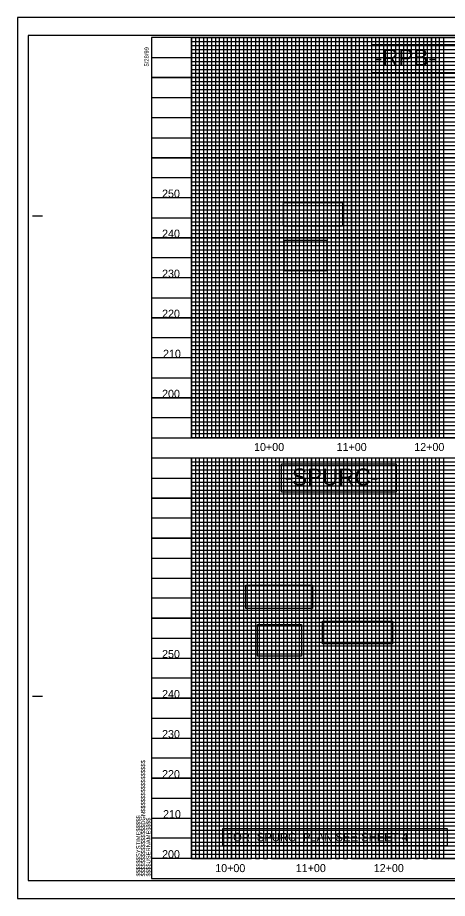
# Model space of a CAD drawing. Extents: x 1810963 to 1812960, y 722070 to 723170.
# Drawn here: x 1810963 to 1811500, y 722070 to 723170 of the extents above; entities that cross this region are included whole.
import ezdxf

# ---------------------------------------------------------------- set-up
doc = ezdxf.new("R2010")
doc.units = 0
for name, color, linetype in [('Exist Horizontal Alignment Tick Label', 7, 'Continuous'), ('Old_Level_11', 7, 'Continuous'), ('Old_Level_2', 7, 'Continuous'), ('Prop Conc 2ft 6in Curb and Gutter', 7, 'Continuous'), ('Prop RDY Traffic Signal CELL', 7, 'Continuous'), ('Prop Shade Heavy', 7, 'Continuous'), ('Prop Shade Light', 7, 'Continuous'), ('Scratch_Level_0', 7, 'Continuous'), ('Scratch_Level_3', 7, 'Continuous'), ('Sheet Block Title CELL', 7, 'Continuous'), ('Sheet Layout Profile Border Port 1', 7, 'Continuous'), ('Sheet Layout Profile Border Port 2', 7, 'Continuous'), ('Sheet North Arrow CELL', 7, 'Continuous'), ('Sheet Symbology CELL', 7, 'Continuous'), ('Sheet Title CELL', 7, 'Continuous')]:
    doc.layers.add(name, color=color, linetype=linetype)

msp = doc.modelspace()

# ---------------------------------------------------------------- linework, layer by layer
at = {"layer": 'Old_Level_11'}
msp.add_lwpolyline([(1810976.5, 722092.3), (1812643, 722092.3), (1812643, 723147.4), (1810976.5, 723147.4)], close=True, dxfattribs=at)
at = {"layer": 'Old_Level_2'}
for points in [[(1811405.7, 723136.4), (1811513.8, 723136.4), (1811513.8, 723101.1), (1811405.7, 723101.1)], [(1811295.4, 722938.9), (1811369.1, 722938.9), (1811369.1, 722909.6), (1811295.4, 722909.6)], [(1811296.2, 722891.9), (1811349.9, 722891.9), (1811349.9, 722853.7), (1811296.2, 722853.7)], [(1811292.9, 722612.7), (1811436.3, 722612.7), (1811436.3, 722577.3), (1811292.9, 722577.3)], [(1811248.4, 722460.9), (1811331.9, 722460.9), (1811331.9, 722431.9), (1811248.4, 722431.9)], [(1811344.1, 722416.3), (1811431.9, 722416.3), (1811431.9, 722388), (1811344.1, 722388)], [(1811263.3, 722411.8), (1811318.2, 722411.8), (1811318.2, 722372.5), (1811263.3, 722372.5)], [(1811219.7, 722157), (1811500.2, 722157), (1811500.2, 722135.4), (1811219.7, 722135.4)]]:
    msp.add_lwpolyline(points, close=True, dxfattribs=at)
at = {"layer": 'Prop Conc 2ft 6in Curb and Gutter'}
for p, q in [((1811180.5, 722644.9), (1811180.5, 723144.9)), ((1811230.5, 722644.9), (1811230.5, 723144.9)), ((1811280.5, 722644.9), (1811280.5, 723144.9)), ((1811330.5, 722644.9), (1811330.5, 723144.9)), ((1811380.5, 722644.9), (1811380.5, 723144.9)), ((1811430.5, 722644.9), (1811430.5, 723144.9)), ((1811480.5, 722644.9), (1811480.5, 723144.9)), ((1812230.4, 723094.9), (1811130.5, 723094.9)), ((1812430.4, 723044.9), (1811130.5, 723044.9)), ((1812430.5, 722994.9), (1811130.5, 722994.9)), ((1812630.5, 722944.9), (1811130.5, 722944.9)), ((1812630.5, 722894.9), (1811130.5, 722894.9)), ((1812630.5, 722844.9), (1811130.5, 722844.9)), ((1812630.5, 722794.9), (1811130.5, 722794.9)), ((1812630.5, 722744.9), (1811130.5, 722744.9)), ((1812630.5, 722694.9), (1811130.5, 722694.9)), ((1811130.5, 722619.9), (1812630.3, 722619.9)), ((1811180.5, 722619.9), (1811180.5, 722119.9)), ((1811230.5, 722619.9), (1811230.5, 722119.9)), ((1811280.5, 722619.9), (1811280.5, 722119.9)), ((1811330.5, 722619.9), (1811330.5, 722119.9)), ((1811380.5, 722619.9), (1811380.5, 722119.9)), ((1811430.5, 722619.9), (1811430.5, 722119.9)), ((1811480.5, 722619.9), (1811480.5, 722119.9)), ((1811130.5, 722569.9), (1812630.3, 722569.9)), ((1811130.5, 722519.9), (1812630.3, 722519.9)), ((1811130.5, 722469.9), (1812630.3, 722469.9)), ((1811130.5, 722419.9), (1812630.3, 722419.9)), ((1811130.5, 722369.9), (1812630.3, 722369.9)), ((1811130.5, 722319.9), (1812630.3, 722319.9)), ((1811130.5, 722269.9), (1812630.3, 722269.9)), ((1811130.5, 722219.9), (1812630.3, 722219.9)), ((1811130.5, 722169.9), (1812630.3, 722169.9))]:
    msp.add_line(p, q, dxfattribs=at)
at = {"layer": 'Prop RDY Traffic Signal CELL'}
for p, q in [((1812647.5, 723169.9), (1810963.5, 723169.9)), ((1810963.5, 723169.9), (1810963.5, 722069.9)), ((1810963.5, 722069.9), (1812647.5, 722069.9))]:
    msp.add_line(p, q, dxfattribs=at)
at = {"layer": 'Prop Shade Heavy'}
msp.add_line((1811130.5, 722119.9), (1811130.5, 722119.9), dxfattribs=at)
for points in [[(1811180.5, 723144.9), (1811180.5, 722644.9), (1811230.5, 722644.9), (1811230.5, 723144.9), (1811280.5, 723144.9), (1811280.5, 722644.9), (1811330.5, 722644.9), (1811330.5, 723144.9), (1811380.5, 723144.9), (1811380.5, 722644.9), (1811430.5, 722644.9), (1811430.5, 723144.9), (1811480.5, 723144.9), (1811480.5, 722644.9), (1811530.5, 722644.9)], [(1811130.5, 723094.9), (1812230.4, 723094.9)], [(1812430.5, 723044.9), (1811130.5, 723044.9), (1811130.5, 722994.9), (1812430.5, 722994.9)], [(1812630.5, 722944.9), (1811130.5, 722944.9), (1811130.5, 722894.9), (1812630.5, 722894.9)], [(1812630.5, 722844.9), (1811130.5, 722844.9), (1811130.5, 722794.9), (1812630.5, 722794.9)], [(1812630.5, 722744.9), (1811130.5, 722744.9), (1811130.5, 722744.9), (1811130.5, 722694.9), (1812630.5, 722694.9)], [(1811180.5, 722619.9), (1811180.5, 722119.9), (1811230.5, 722119.9), (1811230.5, 722619.9), (1811280.5, 722619.9), (1811280.5, 722119.9), (1811330.5, 722119.9), (1811330.5, 722619.9), (1811380.5, 722619.9), (1811380.5, 722119.9), (1811430.5, 722119.9), (1811430.5, 722619.9), (1811480.5, 722619.9), (1811480.5, 722119.9), (1811530.5, 722119.9)], [(1812630.5, 722569.9), (1811130.5, 722569.9)], [(1812630.5, 722519.9), (1811130.5, 722519.9), (1811130.5, 722469.9), (1812630.5, 722469.9)], [(1812630.5, 722419.9), (1811130.5, 722419.9), (1811130.5, 722369.9), (1812630.5, 722369.9)], [(1812630.5, 722319.9), (1811130.5, 722319.9), (1811130.5, 722269.9), (1812630.5, 722269.9)], [(1812630.5, 722219.9), (1811130.5, 722219.9), (1811130.5, 722219.9), (1811130.5, 722169.9), (1812630.5, 722169.9)], [(1812630.5, 722119.9), (1811130.5, 722119.9)]]:
    msp.add_lwpolyline(points, dxfattribs=at)
at = {"layer": 'Prop Shade Light'}
for p, q in [((1811205.5, 723144.9), (1811205.5, 722644.9)), ((1811255.5, 722644.9), (1811255.5, 723144.9)), ((1811255.5, 723144.9), (1811305.5, 723144.9)), ((1811305.5, 723144.9), (1811305.5, 722644.9)), ((1811355.5, 722644.9), (1811355.5, 723144.9)), ((1811355.5, 723144.9), (1811405.5, 723144.9)), ((1811405.5, 723144.9), (1811405.5, 722644.9)), ((1811455.5, 722644.9), (1811455.5, 723144.9)), ((1811455.5, 723144.9), (1811505.5, 723144.9)), ((1811130.5, 723119.9), (1812230.4, 723119.9)), ((1811205.5, 722644.9), (1811255.5, 722644.9)), ((1811305.5, 722644.9), (1811355.5, 722644.9)), ((1811405.5, 722644.9), (1811455.5, 722644.9))]:
    msp.add_line(p, q, dxfattribs=at)
for points in [[(1812430.5, 723069.9), (1811130.5, 723069.9), (1811130.5, 723019.9), (1812430.5, 723019.9)], [(1812630.5, 722969.9), (1811130.5, 722969.9), (1811130.5, 722919.9), (1812455.5, 722919.9)], [(1812630.5, 722869.9), (1811130.5, 722869.9), (1811130.5, 722819.9), (1812630.5, 722819.9)], [(1812630.5, 722769.9), (1811130.5, 722769.9), (1811130.5, 722719.9), (1812630.5, 722719.9)], [(1812630.5, 722669.9), (1811130.5, 722669.9)], [(1811155.5, 722619.9), (1811205.5, 722619.9), (1811205.5, 722119.9), (1811255.5, 722119.9), (1811255.5, 722619.9), (1811305.5, 722619.9), (1811305.5, 722119.9), (1811355.5, 722119.9), (1811355.5, 722619.9), (1811405.5, 722619.9), (1811405.5, 722119.9), (1811455.5, 722119.9), (1811455.5, 722619.9), (1811505.5, 722619.9)], [(1811130.5, 722594.9), (1812630.5, 722594.9)], [(1812630.5, 722544.9), (1811130.5, 722544.9), (1811130.5, 722494.9), (1812630.5, 722494.9)], [(1812630.5, 722444.9), (1811130.5, 722444.9), (1811130.5, 722394.9), (1812630.5, 722394.9)], [(1812630.5, 722344.9), (1811130.5, 722344.9), (1811130.5, 722294.9), (1812630.5, 722294.9)], [(1812630.5, 722244.9), (1811130.5, 722244.9), (1811130.5, 722194.9), (1812630.5, 722194.9)], [(1812630.5, 722144.9), (1811130.5, 722144.9)]]:
    msp.add_lwpolyline(points, dxfattribs=at)
at = {"layer": 'Scratch_Level_3'}
msp.add_lwpolyline([(1811180.5, 723144.9), (1812230.5, 723144.9), (1812230.5, 723092.4), (1812430.5, 723092.4), (1812430.4, 722983.8), (1812580.5, 722983.8), (1812580.5, 722644.9), (1811180.5, 722644.9)], close=True, dxfattribs=at)
at = {"layer": 'Sheet Layout Profile Border Port 1'}
msp.add_lwpolyline([(1811180.5, 722983.8), (1811180.5, 722644.9), (1812580.5, 722644.9), (1812580.5, 722983.8)], dxfattribs=at)
at = {"layer": 'Sheet Layout Profile Border Port 2'}
msp.add_lwpolyline([(1811180.5, 722619.9), (1812580.5, 722619.9), (1812580.5, 722119.9), (1811180.5, 722119.9)], close=True, dxfattribs=at)
at = {"layer": 'Sheet North Arrow CELL'}
msp.add_lwpolyline([(1810963.5, 722069.9), (1812647.5, 722069.9), (1812647.5, 723169.9), (1810963.5, 723169.9)], close=True, dxfattribs=at)
at = {"layer": 'Sheet Symbology CELL'}
for p, q in [((1810982, 722922.4), (1810994.5, 722922.4)), ((1811130.5, 722644.9), (1812630.5, 722644.9)), ((1811130.5, 722619.9), (1812630.5, 722619.9)), ((1810982, 722322.4), (1810994.5, 722322.4)), ((1812630.5, 722119.9), (1811130.5, 722119.9)), ((1811130.5, 722094.9), (1812630.5, 722094.9)), ((1811130.5, 722094.9), (1811130.5, 722094.9)), ((1811130.5, 722094.9), (1811130.5, 722094.9)), ((1811130.5, 722094.9), (1811130.5, 722094.9)), ((1811130.5, 722094.9), (1811130.5, 722094.9)), ((1811130.5, 722094.9), (1811130.5, 722094.9)), ((1811130.5, 722094.9), (1811130.5, 722094.9)), ((1811130.5, 722094.9), (1811130.5, 722094.9))]:
    msp.add_line(p, q, dxfattribs=at)
msp.add_lwpolyline([(1812630.5, 723144.9), (1811130.5, 723144.9), (1811130.5, 722094.9), (1812630.5, 722094.9)], close=True, dxfattribs=at)
msp.add_lwpolyline([(1811161, 722094.9), (1811161, 722094.9)], dxfattribs=at)
at = {"layer": 'Sheet Title CELL'}
for p, q in [((1811180.5, 723139.9), (1812230.4, 723139.9)), ((1811180.5, 723134.9), (1811180.5, 723134.9)), ((1812230.4, 723134.8), (1811180.5, 723134.5)), ((1811180.5, 723129.9), (1812230.4, 723129.9)), ((1812230.4, 723099.9), (1811180.5, 723099.9)), ((1811180.5, 723099.9), (1811180.5, 723089.9)), ((1811180.5, 723089.9), (1812430.5, 723089.9)), ((1812430.4, 723009.9), (1811180.5, 723009.9)), ((1812430.5, 723004.9), (1811180.5, 723004.9)), ((1812430.5, 722999.9), (1811180.5, 722999.9)), ((1811180.5, 722989.9), (1812430.5, 722989.9)), ((1812430.5, 722984.9), (1811180.5, 722984.9)), ((1811180.5, 722979.9), (1812580.5, 722979.9)), ((1812580.5, 722959.9), (1811180.5, 722959.9)), ((1811180.5, 722954.9), (1812580.5, 722954.9)), ((1812580.5, 722934.9), (1811180.5, 722934.9)), ((1811180.5, 722929.9), (1812580.5, 722929.9)), ((1812580.5, 722909.9), (1811180.5, 722909.9)), ((1811180.5, 722904.9), (1812580.5, 722904.9)), ((1812580.5, 722899.9), (1811180.5, 722899.9)), ((1811180.5, 722889.9), (1812580.5, 722889.9)), ((1812580.5, 722884.9), (1811180.5, 722884.9)), ((1811180.5, 722879.9), (1812580.5, 722879.9)), ((1812580.5, 722874.9), (1811180.5, 722874.9)), ((1811180.5, 722864.9), (1812580.5, 722864.9)), ((1812580.5, 722859.9), (1811180.5, 722859.9)), ((1811180.5, 722854.9), (1812580.5, 722854.9)), ((1812580.5, 722849.9), (1811180.5, 722849.9)), ((1811180.5, 722839.9), (1812580.5, 722839.9)), ((1812580.5, 722834.9), (1811180.5, 722834.9)), ((1811180.5, 722829.9), (1812580.5, 722829.9)), ((1812580.5, 722824.9), (1811180.5, 722824.9)), ((1811180.5, 722814.9), (1812580.5, 722814.9)), ((1812580.5, 722809.9), (1811180.5, 722809.9)), ((1811180.5, 722804.9), (1812580.5, 722804.9)), ((1812580.5, 722799.9), (1811180.5, 722799.9)), ((1811180.5, 722789.9), (1812580.5, 722789.9)), ((1812580.5, 722784.9), (1811180.5, 722784.9)), ((1811180.5, 722779.9), (1812580.5, 722779.9)), ((1812580.5, 722774.9), (1811180.5, 722774.9)), ((1811180.5, 722764.9), (1812580.5, 722764.9)), ((1812580.5, 722759.9), (1811180.5, 722759.9)), ((1812580.5, 722754.9), (1811180.5, 722754.9)), ((1812580.5, 722749.9), (1811180.5, 722749.9)), ((1811180.5, 722739.9), (1812580.5, 722739.9)), ((1812580.5, 722734.9), (1811180.5, 722734.9)), ((1811180.5, 722729.9), (1812580.5, 722729.9)), ((1812580.5, 722724.9), (1811180.5, 722724.9)), ((1811180.5, 722714.9), (1812580.5, 722714.9)), ((1812580.5, 722709.9), (1811180.5, 722709.9)), ((1811180.5, 722704.9), (1812580.5, 722704.9)), ((1812580.5, 722699.9), (1811180.5, 722699.9)), ((1811180.5, 722689.9), (1812580.5, 722689.9)), ((1812580.5, 722684.9), (1811180.5, 722684.9)), ((1811180.5, 722679.9), (1812580.5, 722679.9)), ((1812580.5, 722674.9), (1811180.5, 722674.9)), ((1811180.5, 722664.9), (1812580.5, 722664.9)), ((1812580.5, 722659.9), (1811180.5, 722659.9)), ((1811180.5, 722654.9), (1812580.5, 722654.9)), ((1811180.5, 722614.9), (1812580.5, 722614.9)), ((1812580.5, 722609.9), (1811180.5, 722609.9)), ((1811180.5, 722604.9), (1812580.5, 722604.9)), ((1812580.5, 722599.9), (1811180.5, 722599.9)), ((1811180.5, 722589.9), (1812580.5, 722589.9)), ((1812580.5, 722584.9), (1811180.5, 722584.9)), ((1811180.5, 722579.9), (1812580.5, 722579.9)), ((1812580.5, 722574.9), (1811180.5, 722574.9)), ((1811180.5, 722564.9), (1812580.5, 722564.9)), ((1812580.5, 722559.9), (1811180.5, 722559.9)), ((1811180.5, 722554.9), (1812580.5, 722554.9)), ((1812580.5, 722549.9), (1811180.5, 722549.9)), ((1811180.5, 722539.9), (1812580.5, 722539.9)), ((1812580.5, 722534.9), (1811180.5, 722534.9)), ((1811180.5, 722529.9), (1812580.5, 722529.9)), ((1812580.5, 722524.9), (1811180.5, 722524.9)), ((1811180.5, 722514.9), (1812580.5, 722514.9)), ((1812580.5, 722509.9), (1811180.5, 722509.9)), ((1811180.5, 722504.9), (1812580.5, 722504.9)), ((1812580.5, 722499.9), (1811180.5, 722499.9)), ((1811180.5, 722489.9), (1812580.5, 722489.9)), ((1812580.5, 722484.9), (1811180.5, 722484.9)), ((1811180.5, 722479.9), (1812580.5, 722479.9)), ((1812580.5, 722474.9), (1811180.5, 722474.9)), ((1811180.5, 722464.9), (1812580.5, 722464.9)), ((1812580.5, 722459.9), (1811180.5, 722459.9)), ((1811180.5, 722454.9), (1812580.5, 722454.9)), ((1812580.5, 722449.9), (1811180.5, 722449.9)), ((1811180.5, 722439.9), (1812580.5, 722439.9)), ((1812580.5, 722434.9), (1811180.5, 722434.9)), ((1811180.5, 722429.9), (1812580.5, 722429.9)), ((1812580.5, 722424.9), (1811180.5, 722425)), ((1811180.5, 722414.9), (1812580.5, 722414.9)), ((1812580.5, 722409.9), (1811180.5, 722409.9)), ((1811180.5, 722404.9), (1812580.5, 722404.9)), ((1812580.5, 722399.9), (1811180.5, 722399.9)), ((1811180.5, 722389.9), (1812580.5, 722389.9)), ((1812580.5, 722384.9), (1811180.5, 722384.9)), ((1811180.5, 722379.9), (1812580.5, 722379.9)), ((1812580.5, 722374.9), (1811180.5, 722374.9)), ((1811180.5, 722364.9), (1812580.5, 722364.9)), ((1812580.5, 722359.9), (1811180.5, 722359.9)), ((1811180.5, 722354.9), (1812580.5, 722354.9)), ((1812580.5, 722349.9), (1811180.5, 722349.9)), ((1811180.5, 722339.9), (1812580.5, 722339.9)), ((1812580.5, 722334.9), (1811180.5, 722334.9)), ((1811180.5, 722329.9), (1812580.5, 722329.9)), ((1812580.5, 722324.9), (1811180.5, 722324.9)), ((1811180.5, 722314.9), (1812580.5, 722314.9)), ((1812580.5, 722309.9), (1811180.5, 722309.9)), ((1811180.5, 722304.9), (1812580.5, 722304.9)), ((1812580.5, 722299.9), (1811180.5, 722299.9)), ((1811180.5, 722289.9), (1812580.5, 722289.9)), ((1812580.5, 722284.9), (1811180.5, 722284.9)), ((1811180.5, 722279.9), (1812580.5, 722279.9)), ((1812580.5, 722274.9), (1811180.5, 722274.9)), ((1811180.5, 722264.9), (1812580.5, 722264.9)), ((1812580.5, 722259.9), (1811180.5, 722259.9)), ((1811180.5, 722254.9), (1812580.5, 722254.9)), ((1812580.5, 722249.9), (1811180.5, 722249.9)), ((1811180.5, 722239.9), (1812580.5, 722239.9)), ((1812580.5, 722234.9), (1811180.5, 722234.9)), ((1811180.5, 722229.9), (1812580.5, 722229.9)), ((1812580.5, 722224.9), (1811180.5, 722224.9)), ((1811180.5, 722214.9), (1812580.5, 722214.9)), ((1812580.5, 722209.9), (1811180.5, 722209.9)), ((1811180.5, 722204.9), (1812580.5, 722204.9)), ((1812580.5, 722199.9), (1811180.5, 722199.9)), ((1811180.5, 722189.9), (1812580.5, 722189.9)), ((1812580.5, 722184.9), (1811180.5, 722184.9)), ((1811180.5, 722179.9), (1812580.5, 722179.9)), ((1812580.5, 722174.9), (1811180.5, 722174.9)), ((1811180.5, 722164.9), (1812580.5, 722164.9)), ((1812580.5, 722159.9), (1811180.5, 722159.9)), ((1811180.5, 722154.9), (1812580.5, 722154.9)), ((1812580.5, 722149.9), (1811180.5, 722149.9)), ((1811180.5, 722139.9), (1812580.5, 722139.9)), ((1812580.5, 722134.9), (1811180.5, 722134.9)), ((1811180.5, 722129.9), (1812580.5, 722129.9)), ((1811180.5, 722124.9), (1812580.5, 722124.9))]:
    msp.add_line(p, q, dxfattribs=at)
for points in [[(1811185.5, 723144.9), (1811185.5, 722644.9), (1811190.5, 722644.9), (1811190.5, 723144.9), (1811195.5, 723144.9), (1811195.5, 722644.9), (1811200.5, 722644.9), (1811200.5, 723144.9), (1811210.5, 723144.9), (1811210.5, 722644.9), (1811215.5, 722644.9), (1811215.5, 723144.9), (1811220.5, 723144.9), (1811220.5, 722644.9), (1811225.5, 722644.9), (1811235.5, 722644.9), (1811240.5, 722644.9), (1811240.5, 723144.9), (1811245.5, 723144.9), (1811245.5, 722644.9), (1811250.5, 722644.9), (1811250.5, 723144.9), (1811260.5, 723144.9), (1811260.5, 722644.9), (1811265.5, 722644.9), (1811265.5, 723144.9), (1811270.5, 723144.9), (1811270.5, 722644.9), (1811275.5, 722644.9), (1811275.5, 723144.9), (1811285.5, 723144.9), (1811285.5, 722644.9), (1811290.5, 722644.9), (1811290.5, 723144.9), (1811295.5, 723144.9), (1811295.5, 722644.9), (1811300.5, 722644.9), (1811300.5, 723144.9), (1811310.5, 723144.9), (1811310.5, 722644.9), (1811315.5, 722644.9), (1811315.5, 723144.9), (1811320.5, 723144.9), (1811320.5, 722644.9), (1811325.5, 722644.9), (1811325.5, 723144.9), (1811335.5, 723144.9), (1811335.5, 722644.9), (1811340.5, 722644.9), (1811340.5, 723144.9), (1811345.5, 723144.9), (1811345.5, 722644.9), (1811350.5, 722644.9), (1811350.5, 723144.9), (1811360.5, 723144.9), (1811360.5, 722644.9), (1811365.5, 722644.9), (1811365.5, 723144.9), (1811370.5, 723144.9), (1811370.5, 722644.9), (1811375.5, 722644.9), (1811375.5, 723144.9), (1811385.5, 723144.9), (1811385.5, 722644.9), (1811390.5, 722644.9), (1811390.5, 723144.9), (1811395.5, 723144.9), (1811395.5, 722644.9)], [(1811225.5, 722644.9), (1811225.5, 723144.9), (1811235.5, 723144.9), (1811235.5, 722644.9)], [(1811395.5, 722644.9), (1811400.5, 722644.9), (1811400.5, 723144.9), (1811410.5, 723144.9), (1811410.5, 722644.9), (1811415.5, 722644.9), (1811415.5, 723144.9), (1811420.5, 723144.9), (1811420.5, 722644.9), (1811425.5, 722644.9), (1811425.5, 723144.9), (1811435.5, 723144.9), (1811435.5, 722644.9), (1811440.5, 722644.9), (1811440.5, 723144.9), (1811445.5, 723144.9), (1811445.5, 722644.9), (1811450.5, 722644.9), (1811450.5, 723144.9), (1811460.5, 723144.9), (1811460.5, 722644.9), (1811465.5, 722644.9), (1811465.5, 723144.9), (1811470.5, 723144.9), (1811470.5, 722644.9), (1811475.5, 722644.9), (1811475.5, 723144.9), (1811485.5, 723144.9), (1811485.5, 722644.9), (1811490.5, 722644.9), (1811490.5, 723144.9), (1811495.5, 723144.9), (1811495.5, 722644.9), (1811500.5, 722644.9)], [(1812230.4, 723124.9), (1811180.5, 723124.9), (1811180.5, 723114.9), (1812230.4, 723114.9)], [(1812230.4, 723109.9), (1811180.5, 723109.9), (1811180.5, 723104.9), (1812230.4, 723104.9)], [(1812430.5, 723084.9), (1811180.5, 723084.9), (1811180.5, 723079.9), (1812430.5, 723079.9)], [(1812430.5, 723074.9), (1811180.5, 723074.9), (1811180.5, 723064.9), (1812430.5, 723064.9)], [(1812430.5, 723059.9), (1811180.5, 723059.9), (1811180.5, 723054.9), (1812430.5, 723054.9)], [(1812430.5, 723049.9), (1811180.5, 723049.9), (1811180.5, 723039.9), (1812430.5, 723039.9)], [(1812430.5, 723034.8), (1811180.6, 723034.8), (1811180.6, 723029.9), (1812430.5, 723029.9)], [(1812430.5, 723024.9), (1811180.5, 723024.9), (1811180.5, 723014.9), (1812430.5, 723014.9)], [(1812580.5, 722974.9), (1811180.5, 722974.9), (1811180.5, 722964.9), (1812580.5, 722964.9)], [(1812580.5, 722949.9), (1811180.5, 722949.9), (1811180.5, 722939.9), (1812580.5, 722939.9)], [(1812580.5, 722924.9), (1811180.5, 722924.9), (1811180.5, 722914.9), (1812580.5, 722914.9)], [(1812580.5, 722649.9), (1811180.5, 722649.9)], [(1811180.5, 722619.9), (1811185.5, 722619.9), (1811185.5, 722119.9), (1811190.5, 722119.9), (1811190.5, 722619.9), (1811195.5, 722619.9), (1811195.5, 722119.9), (1811200.5, 722119.9), (1811200.5, 722619.9), (1811210.5, 722619.9), (1811210.5, 722119.9), (1811215.5, 722119.9), (1811215.5, 722619.9), (1811220.5, 722619.9), (1811220.5, 722119.9), (1811225.5, 722119.9), (1811235.5, 722119.9), (1811240.5, 722119.9), (1811240.5, 722619.9), (1811245.5, 722619.9), (1811245.5, 722119.9), (1811250.5, 722119.9), (1811250.5, 722619.9), (1811260.5, 722619.9), (1811260.5, 722119.9), (1811265.5, 722119.9), (1811265.5, 722619.9), (1811270.5, 722619.9), (1811270.5, 722119.9), (1811275.5, 722119.9), (1811275.5, 722619.9), (1811285.5, 722619.9), (1811285.5, 722119.9), (1811290.5, 722119.9), (1811290.5, 722619.9), (1811295.5, 722619.9), (1811295.5, 722119.9), (1811300.5, 722119.9), (1811300.5, 722619.9), (1811310.5, 722619.9), (1811310.5, 722119.9), (1811315.5, 722119.9), (1811315.5, 722619.9), (1811320.5, 722619.9), (1811320.5, 722119.9), (1811325.5, 722119.9), (1811325.5, 722619.9), (1811335.5, 722619.9), (1811335.5, 722119.9), (1811340.5, 722119.9), (1811340.5, 722619.9), (1811345.5, 722619.9), (1811345.5, 722119.9), (1811350.5, 722119.9), (1811350.5, 722619.9), (1811360.5, 722619.9), (1811360.5, 722119.9), (1811365.5, 722119.9), (1811365.5, 722619.9), (1811370.5, 722619.9), (1811370.5, 722119.9), (1811375.5, 722119.9), (1811375.5, 722619.9), (1811385.5, 722619.9), (1811385.5, 722119.9), (1811390.5, 722119.9), (1811390.5, 722619.9), (1811395.5, 722619.9), (1811395.5, 722119.9)], [(1811225.5, 722119.9), (1811225.5, 722619.9), (1811235.5, 722619.9), (1811235.5, 722119.9)], [(1811395.5, 722119.9), (1811400.5, 722119.9), (1811400.5, 722619.9), (1811410.5, 722619.9), (1811410.5, 722119.9), (1811415.5, 722119.9), (1811415.5, 722619.9), (1811420.5, 722619.9), (1811420.5, 722119.9), (1811425.5, 722119.9), (1811425.5, 722619.9), (1811435.5, 722619.9), (1811435.5, 722119.9), (1811440.5, 722119.9), (1811440.5, 722619.9), (1811445.5, 722619.9), (1811445.5, 722119.9), (1811450.5, 722119.9), (1811450.5, 722619.9), (1811460.5, 722619.9), (1811460.5, 722119.9), (1811465.5, 722119.9), (1811465.5, 722619.9), (1811470.5, 722619.9), (1811470.5, 722119.9), (1811475.5, 722119.9), (1811475.5, 722619.9), (1811485.5, 722619.9), (1811485.5, 722119.9), (1811490.5, 722119.9), (1811490.5, 722619.9), (1811495.5, 722619.9), (1811495.5, 722119.9), (1811500.5, 722119.9)]]:
    msp.add_lwpolyline(points, dxfattribs=at)

# ---------------------------------------------------------------- texts
at = {"layer": 'Exist Horizontal Alignment Tick Label'}
for s, height, p in [('-RPB-', 21, (1811409.5, 723109.5)), ('-SPURC-', 21, (1811296.9, 722585.7)), ('FOR -SPURC- PLAN SEE SHEET 4', 10.5, (1811224, 722141.2))]:
    msp.add_text(s, height=height, rotation=360, dxfattribs=at).set_placement(p)
at = {"layer": 'Scratch_Level_0'}
for s, p in [('250', (1811143.9, 722945.1)), ('240', (1811143.9, 722895.1)), ('230', (1811143.9, 722845.1)), ('220', (1811143.9, 722795.1)), ('210', (1811145.1, 722745.1)), ('200', (1811143.9, 722695.1)), ('250', (1811143.9, 722370.1)), ('240', (1811143.9, 722320.1)), ('230', (1811143.9, 722270.1)), ('220', (1811143.9, 722220.1)), ('210', (1811145.1, 722170.1)), ('200', (1811143.9, 722120.1))]:
    msp.add_text(s, height=10, dxfattribs=at).set_placement(p)
at = {"layer": 'Sheet Block Title CELL'}
for s, p in [('10+00', (1811258.8, 722628.6)), ('11+00', (1811361.9, 722628.6)), ('12+00', (1811458.9, 722628.6)), ('10+00', (1811210.3, 722102.7)), ('11+00', (1811310.9, 722102.7)), ('12+00', (1811408.3, 722102.7))]:
    msp.add_text(s, height=10, dxfattribs=at).set_placement(p)
at = {"layer": 'Sheet Symbology CELL'}
for s, p in [('5/28/99', (1811127.2, 723108.8)), ('$$$$$$$$$$$$$$$$DGN$$$$$$$$$$$$$$$$', (1811122.8, 722097.3)), ('$$$$$$SYSTIME$$$$$', (1811116.8, 722097.3)), ('$$$$USERNAME$$$$', (1811129.4, 722097.3))]:
    msp.add_text(s, height=5.25, rotation=90, dxfattribs=at).set_placement(p)

doc.saveas('drawing.dxf')
